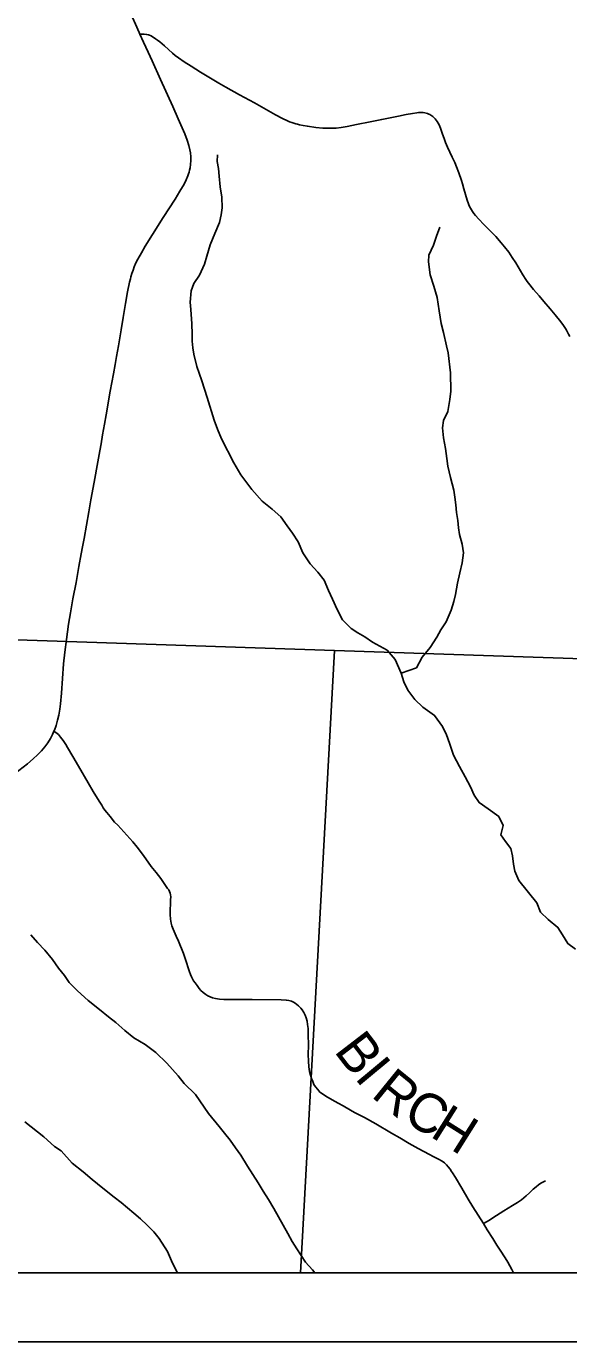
# Model space of a CAD drawing. Extents: x -14196 to 143, y -6096 to 28.
# Drawn here: x 62.952 to 63.739, y 16.799 to 18.706 of the extents above; entities that cross this region are included whole.
import ezdxf

# ---------------------------------------------------------------- set-up
doc = ezdxf.new("R2010")
doc.units = 0
for name, color, linetype in [('GM_X_Corporation', 7, 'Continuous'), ('GM_X_County_Road', 7, 'Continuous'), ('GM_X_Minor_River', 7, 'Continuous'), ('GM_X_Township_Road', 7, 'Continuous'), ('GM_X_Township_Road_Text', 7, 'Continuous'), ('SH_Data', 7, 'Continuous')]:
    doc.layers.add(name, color=color, linetype=linetype)

msp = doc.modelspace()

# ---------------------------------------------------------------- linework, layer by layer
at = {"layer": 'GM_X_Corporation'}
for points in [[(58.1028, 16.8985), (64.9028, 16.8985), (64.9028, 18.7286), (64.4266, 18.7347), (64.3696, 18.7343), (63.6879, 18.7414), (63.0887, 18.7577), (62.5403, 18.7731)], [(62.3117, 16.8985), (64.9028, 16.8985), (64.9028, 18.7286), (64.4266, 18.7347), (64.3696, 18.7343), (63.6879, 18.7414), (63.0887, 18.7577), (62.5403, 18.7731)]]:
    msp.add_lwpolyline(points, dxfattribs=at)
for points in [[(62.3171, 16.8985), (63.3498, 16.8985), (63.3993, 17.801), (62.3495, 17.8363), (62.3192, 16.9598)], [(63.3498, 16.8985), (64.3679, 16.8985), (64.394, 17.7675), (63.3993, 17.801)]]:
    msp.add_lwpolyline(points, close=True, dxfattribs=at)
at = {"layer": 'GM_X_County_Road'}
for points in [[(63.1169, 18.6949), (63.1157, 18.6976), (63.1104, 18.7095), (63.106, 18.7191), (63.0975, 18.7377), (63.0889, 18.7572)], [(62.9922, 17.6842), (62.9928, 17.6857), (62.9952, 17.6922), (62.9975, 17.6999), (62.9992, 17.7072), (63.0008, 17.7158), (63.0019, 17.7239), (63.0032, 17.7394), (63.0046, 17.7605), (63.0061, 17.7815), (63.0078, 17.7988), (63.0102, 17.817), (63.0135, 17.8393), (63.0162, 17.8559), (63.0198, 17.876), (63.0243, 17.8998), (63.0285, 17.9231), (63.0318, 17.9414), (63.0336, 17.9512), (63.0358, 17.9634), (63.0428, 18.0024), (63.0457, 18.0195), (63.0505, 18.045), (63.0558, 18.0749), (63.0586, 18.0908), (63.0605, 18.1006), (63.0628, 18.114), (63.0654, 18.1293), (63.0678, 18.1428), (63.0739, 18.177), (63.0786, 18.2026), (63.0809, 18.2161), (63.0829, 18.2277), (63.0856, 18.243), (63.0897, 18.2663), (63.0927, 18.284), (63.096, 18.3042), (63.099, 18.3213), (63.1019, 18.3352), (63.103, 18.34), (63.1038, 18.343), (63.1053, 18.3478), (63.1069, 18.3527), (63.1087, 18.3576), (63.1111, 18.3632), (63.1139, 18.3687), (63.119, 18.3779), (63.1247, 18.3875), (63.1352, 18.4043), (63.1508, 18.429), (63.1678, 18.4557), (63.175, 18.4673), (63.1809, 18.4775), (63.184, 18.4837), (63.1864, 18.4895), (63.1874, 18.4923), (63.1881, 18.4949), (63.1889, 18.4979), (63.1896, 18.501), (63.1903, 18.506), (63.1907, 18.5116), (63.1906, 18.5173), (63.1901, 18.5229), (63.1894, 18.5273), (63.188, 18.5334), (63.1855, 18.5411), (63.182, 18.5504), (63.1726, 18.5721), (63.1644, 18.5902), (63.1466, 18.6292), (63.1345, 18.6564), (63.1287, 18.6687), (63.1221, 18.6834), (63.1169, 18.6949)], [(63.7403, 18.2566), (63.7388, 18.2598), (63.7373, 18.2628), (63.7359, 18.2655), (63.7342, 18.2682), (63.7314, 18.2724), (63.7273, 18.2779), (63.7192, 18.2881), (63.7121, 18.2967), (63.7028, 18.3074), (63.6959, 18.3153), (63.6879, 18.3247), (63.6805, 18.3339), (63.6786, 18.3364), (63.6765, 18.3394), (63.6722, 18.3461), (63.6621, 18.3632), (63.6571, 18.3711), (63.6518, 18.3788), (63.6459, 18.3868), (63.6411, 18.3925), (63.6332, 18.4014), (63.6246, 18.4104), (63.6158, 18.4192), (63.6084, 18.4267), (63.6035, 18.4322), (63.6015, 18.4348), (63.5994, 18.4376), (63.5977, 18.4402), (63.5962, 18.4428), (63.5946, 18.4458), (63.5933, 18.4488), (63.5916, 18.4541), (63.5869, 18.4708), (63.5849, 18.4779), (63.5835, 18.4826), (63.5797, 18.4938), (63.5763, 18.5025), (63.5736, 18.5088), (63.5699, 18.5167), (63.5629, 18.5312), (63.56, 18.538), (63.5585, 18.5421), (63.5553, 18.5515), (63.5529, 18.5586), (63.551, 18.5633), (63.5497, 18.5658), (63.5483, 18.5683), (63.5468, 18.5704), (63.5454, 18.5721), (63.5439, 18.5738), (63.542, 18.5755), (63.5405, 18.5767), (63.5389, 18.5777), (63.5374, 18.5785), (63.5359, 18.5792), (63.5342, 18.5799), (63.5323, 18.5804), (63.5301, 18.5809), (63.528, 18.5812), (63.5261, 18.5813), (63.5242, 18.5813), (63.5212, 18.5812), (63.5185, 18.581), (63.5123, 18.5801), (63.5031, 18.5784), (63.4921, 18.5761), (63.4678, 18.5714), (63.4509, 18.5681), (63.4309, 18.564), (63.4176, 18.5613), (63.409, 18.5598), (63.4017, 18.5589), (63.3962, 18.5586), (63.3926, 18.5585), (63.3894, 18.5585), (63.3856, 18.5586), (63.382, 18.5588), (63.3722, 18.5598), (63.3599, 18.5615), (63.3535, 18.5626), (63.3483, 18.5637), (63.3455, 18.5644), (63.343, 18.5651), (63.3402, 18.5659), (63.3371, 18.5669), (63.3338, 18.5681), (63.3308, 18.5694), (63.3235, 18.5727), (63.3137, 18.5779), (63.3067, 18.5819), (63.283, 18.5954), (63.2611, 18.6072), (63.2416, 18.618), (63.2314, 18.624), (63.2048, 18.64), (63.191, 18.6484), (63.1811, 18.6547), (63.1727, 18.6606), (63.1678, 18.6643), (63.1642, 18.6673), (63.1523, 18.678), (63.1456, 18.6837), (63.1425, 18.6862), (63.1396, 18.6883), (63.1375, 18.6897), (63.1349, 18.6913), (63.1331, 18.6924), (63.131, 18.6934), (63.1291, 18.694), (63.1265, 18.6946), (63.1231, 18.695), (63.1197, 18.6951), (63.1169, 18.6949)], [(62.9266, 17.6158), (62.9412, 17.627), (62.9539, 17.6369), (62.962, 17.6437), (62.9685, 17.6497), (62.9741, 17.6555), (62.979, 17.6612), (62.9834, 17.6673), (62.987, 17.6732), (62.9901, 17.6794), (62.9922, 17.6842)]]:
    msp.add_lwpolyline(points, dxfattribs=at)
at = {"layer": 'GM_X_Minor_River'}
for points in [[(63.6925, 17.4351), (63.6663, 17.4674), (63.6609, 17.4809), (63.6589, 17.4911), (63.6573, 17.5032), (63.6549, 17.5138), (63.6473, 17.524), (63.6404, 17.5338), (63.644, 17.5471), (63.6375, 17.5603), (63.6222, 17.5715), (63.6089, 17.5805), (63.6016, 17.5914), (63.5962, 17.6035), (63.5885, 17.6178), (63.5805, 17.6329), (63.572, 17.6491), (63.5658, 17.6665), (63.5615, 17.6786), (63.5557, 17.6907), (63.5443, 17.7069), (63.5275, 17.7189), (63.5157, 17.7301), (63.5057, 17.7433), (63.4995, 17.7558), (63.496, 17.7683), (63.4872, 17.7879), (63.4753, 17.8014), (63.4544, 17.813), (63.4433, 17.8209), (63.4331, 17.8265), (63.4235, 17.8329), (63.4106, 17.8457), (63.4029, 17.8604), (63.3963, 17.8755), (63.3905, 17.888), (63.384, 17.9031), (63.3752, 17.9148), (63.3637, 17.9268), (63.3533, 17.9426), (63.3464, 17.9585), (63.3383, 17.9713), (63.3307, 17.9819), (63.3215, 17.9951), (63.3089, 18.006), (63.2944, 18.0176), (63.2791, 18.0346), (63.2634, 18.0561), (63.2531, 18.0734), (63.2354, 18.1082), (63.2296, 18.1221), (63.2245, 18.135), (63.2144, 18.1679), (63.2066, 18.1921), (63.2028, 18.2031), (63.1993, 18.2129), (63.195, 18.2307), (63.1934, 18.2402), (63.1929, 18.2496), (63.1928, 18.2599), (63.1923, 18.2747), (63.1907, 18.2959), (63.1898, 18.3061), (63.1912, 18.3228), (63.1949, 18.3335), (63.2031, 18.3457), (63.2106, 18.3613), (63.2139, 18.3731), (63.2187, 18.3894), (63.2254, 18.4058), (63.2321, 18.4217), (63.2346, 18.4331), (63.2364, 18.443), (63.2355, 18.4586), (63.2335, 18.4737), (63.2319, 18.4892), (63.231, 18.5002), (63.2291, 18.5105), (63.2294, 18.5199)], [(63.496, 17.7683), (63.5179, 17.776), (63.5265, 17.7912), (63.5378, 17.8053), (63.5475, 17.8206), (63.5535, 17.8312), (63.5613, 17.8426), (63.5684, 17.8594), (63.5724, 17.8723), (63.5746, 17.8822), (63.5775, 17.8985), (63.5808, 17.9137), (63.5845, 17.9281), (63.5862, 17.9425), (63.5842, 17.9554), (63.5803, 17.9694), (63.5791, 17.9788), (63.5779, 17.9898), (63.5763, 18.0012), (63.5751, 18.0125), (63.5738, 18.0235), (63.5722, 18.0334), (63.5676, 18.0519), (63.5636, 18.0686), (63.562, 18.0796), (63.56, 18.0943), (63.5572, 18.1095), (63.5556, 18.1242), (63.5574, 18.1345), (63.5637, 18.1478), (63.5666, 18.1649), (63.5677, 18.177), (63.5675, 18.2036), (63.5642, 18.2328), (63.5618, 18.243), (63.5571, 18.2623), (63.554, 18.2755), (63.5512, 18.2937), (63.5496, 18.3036), (63.548, 18.313), (63.5433, 18.3297), (63.5379, 18.3459), (63.5355, 18.3649), (63.5358, 18.3744), (63.5429, 18.3888), (63.5469, 18.4021), (63.5517, 18.4151)], [(63.7485, 17.3681), (63.7375, 17.376), (63.7301, 17.3888), (63.7232, 17.3993), (63.709, 17.411), (63.6979, 17.4215), (63.6925, 17.4351)], [(63.3704, 16.8985), (63.367, 16.9028), (63.357, 16.9141), (63.3444, 16.9332), (63.3378, 16.9441), (63.3313, 16.9554), (63.3248, 16.9675), (63.3179, 16.9795), (63.3113, 16.9919), (63.3036, 17.0047), (63.2959, 17.0167), (63.2886, 17.0288), (63.2806, 17.0408), (63.2729, 17.0532), (63.2633, 17.069), (63.2556, 17.0799), (63.2476, 17.0908), (63.2396, 17.101), (63.2319, 17.1108), (63.2162, 17.1295), (63.1974, 17.157), (63.181, 17.1731), (63.1722, 17.184), (63.1558, 17.2024), (63.1401, 17.2182), (63.1245, 17.2298), (63.1081, 17.2395), (63.0951, 17.25), (63.0818, 17.2613), (63.0715, 17.2699), (63.0581, 17.2804), (63.0418, 17.2935), (63.0265, 17.3074), (63.0143, 17.3194), (63.0077, 17.3295), (62.9989, 17.3401), (62.9901, 17.3529), (62.979, 17.3664), (62.9683, 17.3777), (62.9584, 17.3886)], [(63.1713, 16.8985), (63.1643, 16.9122), (63.157, 16.9292), (63.1447, 16.9483), (63.137, 16.9581), (63.1275, 16.9675), (63.1175, 16.9769), (63.108, 16.9851), (63.0897, 17.0004), (63.0794, 17.0083), (63.063, 17.0214), (63.0478, 17.0338), (63.0344, 17.045), (63.0188, 17.0577), (63.0027, 17.0754), (62.9928, 17.0817), (62.9775, 17.0956), (62.9501, 17.1173)]]:
    msp.add_lwpolyline(points, dxfattribs=at)
at = {"layer": 'GM_X_Township_Road'}
for points in [[(63.6151, 16.9699), (63.6076, 16.982), (63.6, 16.9941), (63.5931, 17.0052), (63.5837, 17.0213), (63.5747, 17.0369), (63.5701, 17.0435), (63.5688, 17.0456), (63.5668, 17.0488), (63.5642, 17.0523), (63.5618, 17.0551), (63.5586, 17.058), (63.5551, 17.0606), (63.5502, 17.0634), (63.5424, 17.0671), (63.5369, 17.0699), (63.5205, 17.0788), (63.5076, 17.0862), (63.4941, 17.094), (63.4818, 17.1012), (63.4593, 17.1143), (63.4425, 17.1236), (63.4283, 17.1312), (63.4224, 17.1345), (63.4116, 17.1405), (63.4046, 17.1445), (63.3959, 17.1493), (63.3867, 17.1545), (63.3815, 17.1579), (63.3781, 17.1606), (63.3748, 17.1642), (63.3717, 17.1682), (63.3694, 17.1718), (63.3675, 17.1757), (63.3656, 17.1803), (63.3642, 17.185), (63.363, 17.1904), (63.3621, 17.1972), (63.3614, 17.2052), (63.3611, 17.2151), (63.3612, 17.2288), (63.3611, 17.2443), (63.3608, 17.253), (63.3602, 17.2586), (63.3593, 17.2635), (63.358, 17.2682), (63.3565, 17.2723), (63.3545, 17.2762), (63.3522, 17.2799), (63.3505, 17.2821), (63.3489, 17.2839), (63.347, 17.2858), (63.3447, 17.2876), (63.342, 17.2896), (63.3396, 17.2911), (63.3366, 17.2923), (63.3331, 17.2933), (63.3291, 17.294), (63.3217, 17.2942), (63.2798, 17.2948), (63.2466, 17.2949), (63.2385, 17.2951), (63.2322, 17.2955), (63.2266, 17.2964), (63.2224, 17.2975), (63.2189, 17.2987), (63.2155, 17.3003), (63.2124, 17.3022), (63.2084, 17.3052), (63.2054, 17.3081), (63.2029, 17.311), (63.1997, 17.3152), (63.1968, 17.319), (63.1947, 17.3221), (63.193, 17.3249), (63.1915, 17.3279), (63.1902, 17.3309), (63.1888, 17.3352), (63.1825, 17.3545), (63.18, 17.3615), (63.1728, 17.3793), (63.1695, 17.3867), (63.1649, 17.3969), (63.1632, 17.4016), (63.1621, 17.4058), (63.1614, 17.4113), (63.1609, 17.4181), (63.1608, 17.4256), (63.1611, 17.433), (63.1614, 17.4393), (63.1615, 17.4438), (63.1612, 17.4466), (63.1606, 17.4491), (63.1597, 17.4514), (63.1586, 17.4538), (63.1571, 17.4561), (63.1521, 17.4631), (63.1471, 17.4702), (63.1403, 17.4791), (63.1334, 17.4879), (63.1223, 17.5035), (63.1129, 17.5158), (63.1067, 17.5234), (63.0981, 17.5332), (63.0848, 17.5475), (63.0801, 17.5523), (63.0735, 17.5602), (63.0689, 17.566), (63.0662, 17.5696), (63.0638, 17.573), (63.0614, 17.5766), (63.0576, 17.5826), (63.0492, 17.5968), (63.0419, 17.6093), (63.0278, 17.6333), (63.0197, 17.6471), (63.012, 17.6605), (63.0094, 17.6647), (63.0057, 17.6705), (63.0019, 17.6754), (62.9986, 17.6791), (62.9966, 17.6806), (62.9922, 17.6842)], [(63.6151, 16.9699), (63.6239, 16.975), (63.6286, 16.978), (63.6447, 16.9884), (63.6573, 16.9961), (63.6647, 17.0006), (63.6703, 17.0045), (63.677, 17.0099), (63.6821, 17.0144), (63.6874, 17.0196), (63.6915, 17.0233), (63.6949, 17.026), (63.6986, 17.0283), (63.705, 17.0318)], [(63.6589, 16.8985), (63.6565, 16.9033), (63.6505, 16.9141), (63.6466, 16.9204), (63.6393, 16.9313), (63.6346, 16.9385), (63.6287, 16.948), (63.6208, 16.9607), (63.6151, 16.9699)]]:
    msp.add_lwpolyline(points, dxfattribs=at)
at = {"layer": 'SH_Data'}
for p, q in [((58.1028, 16.8985), (64.9028, 16.8985)), ((58.0028, 16.7985), (65.0028, 16.7985))]:
    msp.add_line(p, q, dxfattribs=at)

# ---------------------------------------------------------------- texts
at = {"layer": 'GM_X_Township_Road_Text'}
for s, rotation, p in [('B', 307.5803, (63.3973, 17.2201)), ('I', 309.7203, (63.4272, 17.1813)), ('R', 320.9089, (63.4507, 17.1548)), ('C', 331.0948, (63.4961, 17.1192)), ('H', 327.7811, (63.5362, 17.0971))]:
    msp.add_text(s, height=0.0568, rotation=rotation, dxfattribs=at).set_placement(p)

doc.saveas('drawing.dxf')
